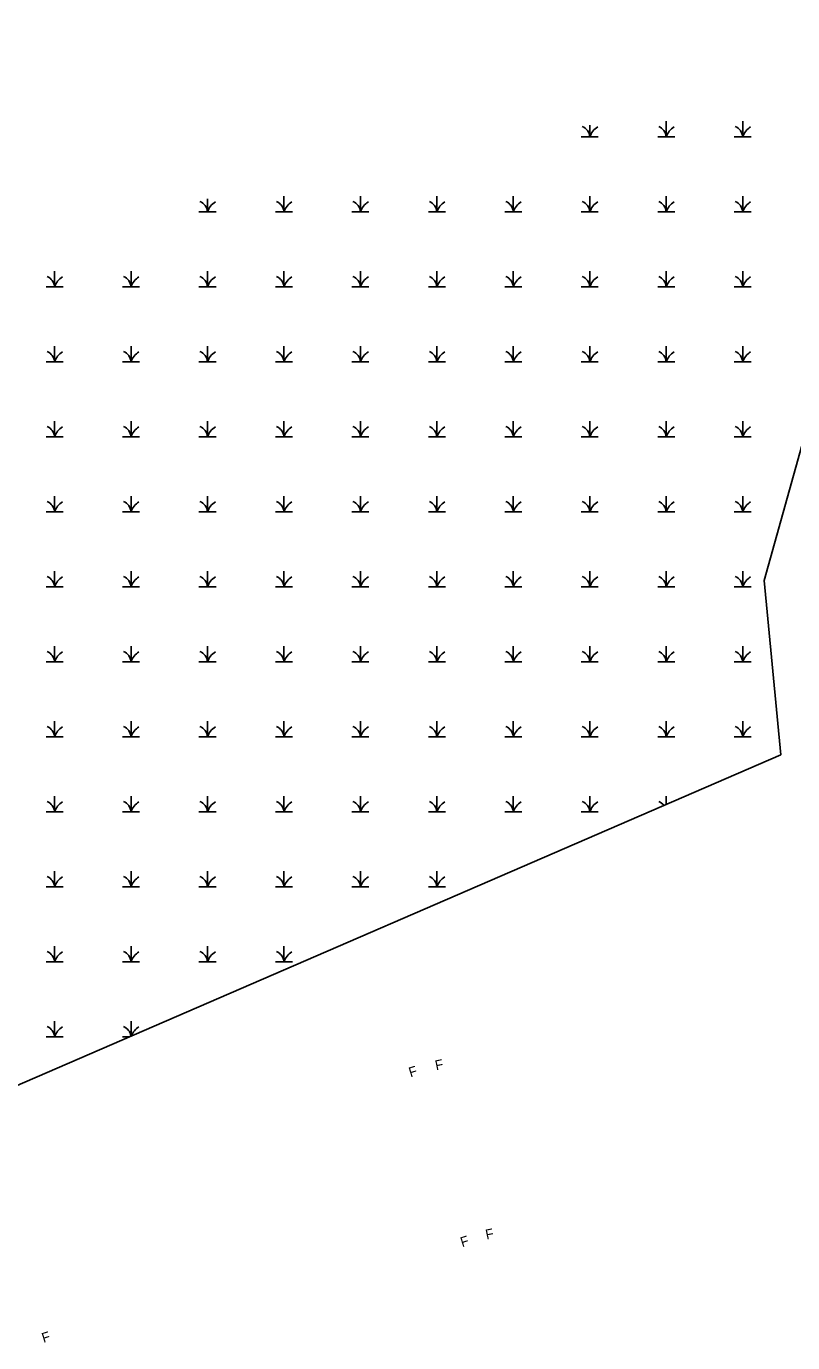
# Model space of a CAD drawing. Extents: x 2166958 to 2178986, y 64620 to 71122.
# Drawn here: x 2168096 to 2168483, y 65520 to 66185 of the extents above; entities that cross this region are included whole.
import ezdxf

# ---------------------------------------------------------------- set-up
doc = ezdxf.new("R2010")
doc.units = 0
for name, color, linetype in [('Default', 7, 'Continuous'), ('Prop Horizontal Alignment', 7, 'Continuous'), ('Prop Horizontal Alignment Station Label', 7, 'Continuous')]:
    doc.layers.add(name, color=color, linetype=linetype)

msp = doc.modelspace()

# ---------------------------------------------------------------- linework, layer by layer
at = {"layer": 'Prop Horizontal Alignment'}
for points in [[(2168476.74, 65816.71), (2168468.47, 65904.83), (2168496.06, 66003.65), (2168524.17, 66100.17), (2168638.33, 66184.78)], [(2168476.74, 65816.71), (2168078.65, 65644.28), (2168068.11, 65657.94), (2168084.89, 65699.98), (2168086.36, 65730.25), (2168062.03, 65791.53), (2168021.16, 65803.33), (2168001.62, 65820.59), (2167975.63, 65861.24), (2167927.1, 65912.33), (2167919.81, 65940.77), (2167923.18, 65952.74), (2167921.92, 65985.66), (2167915.23, 66044.99)]]:
    msp.add_lwpolyline(points, dxfattribs=at)
at = {"layer": 'Prop Horizontal Alignment Station Label'}
for p, q in [((2168418.95, 66128.92), (2168418.95, 66136.82)), ((2168457.56, 66128.92), (2168457.56, 66136.82)), ((2168380.35, 66128.92), (2168380.35, 66134.91)), ((2168376.05, 66128.92), (2168384.65, 66128.92)), ((2168414.65, 66128.92), (2168423.25, 66128.92)), ((2168453.25, 66128.92), (2168461.86, 66128.92)), ((2168187.34, 66091.03), (2168187.34, 66097.6)), ((2168225.95, 66091.03), (2168225.95, 66098.92)), ((2168264.55, 66091.03), (2168264.55, 66098.92)), ((2168303.15, 66091.03), (2168303.15, 66098.92)), ((2168341.75, 66091.03), (2168341.75, 66098.92)), ((2168380.35, 66091.03), (2168380.35, 66098.92)), ((2168418.95, 66091.03), (2168418.95, 66098.92)), ((2168457.56, 66091.03), (2168457.56, 66098.92)), ((2168183.04, 66091.03), (2168191.65, 66091.03)), ((2168221.65, 66091.03), (2168230.25, 66091.03)), ((2168260.25, 66091.03), (2168268.85, 66091.03)), ((2168298.85, 66091.03), (2168307.45, 66091.03)), ((2168337.45, 66091.03), (2168346.05, 66091.03)), ((2168376.05, 66091.03), (2168384.65, 66091.03)), ((2168414.65, 66091.03), (2168423.25, 66091.03)), ((2168453.25, 66091.03), (2168461.86, 66091.03)), ((2168110.14, 66053.14), (2168110.14, 66061.03)), ((2168148.74, 66053.14), (2168148.74, 66061.03)), ((2168187.34, 66053.14), (2168187.34, 66061.03)), ((2168225.95, 66053.14), (2168225.95, 66061.03)), ((2168264.55, 66053.14), (2168264.55, 66061.03)), ((2168303.15, 66053.14), (2168303.15, 66061.03)), ((2168341.75, 66053.14), (2168341.75, 66061.03)), ((2168380.35, 66053.14), (2168380.35, 66061.03)), ((2168418.95, 66053.14), (2168418.95, 66061.03)), ((2168457.56, 66053.14), (2168457.56, 66061.03)), ((2168105.84, 66053.14), (2168114.44, 66053.14)), ((2168144.44, 66053.14), (2168153.04, 66053.14)), ((2168183.04, 66053.14), (2168191.65, 66053.14)), ((2168221.65, 66053.14), (2168230.25, 66053.14)), ((2168260.25, 66053.14), (2168268.85, 66053.14)), ((2168298.85, 66053.14), (2168307.45, 66053.14)), ((2168337.45, 66053.14), (2168346.05, 66053.14)), ((2168376.05, 66053.14), (2168384.65, 66053.14)), ((2168414.65, 66053.14), (2168423.25, 66053.14)), ((2168453.25, 66053.14), (2168461.86, 66053.14)), ((2168110.14, 66015.25), (2168110.14, 66023.14)), ((2168148.74, 66015.25), (2168148.74, 66023.14)), ((2168187.34, 66015.25), (2168187.34, 66023.14)), ((2168225.95, 66015.25), (2168225.95, 66023.14)), ((2168264.55, 66015.25), (2168264.55, 66023.14)), ((2168303.15, 66015.25), (2168303.15, 66023.14)), ((2168341.75, 66015.25), (2168341.75, 66023.14)), ((2168380.35, 66015.25), (2168380.35, 66023.14)), ((2168418.95, 66015.25), (2168418.95, 66023.14)), ((2168457.56, 66015.25), (2168457.56, 66023.14)), ((2168105.84, 66015.25), (2168114.44, 66015.25)), ((2168144.44, 66015.25), (2168153.04, 66015.25)), ((2168183.04, 66015.25), (2168191.65, 66015.25)), ((2168221.65, 66015.25), (2168230.25, 66015.25)), ((2168260.25, 66015.25), (2168268.85, 66015.25)), ((2168298.85, 66015.25), (2168307.45, 66015.25)), ((2168337.45, 66015.25), (2168346.05, 66015.25)), ((2168376.05, 66015.25), (2168384.65, 66015.25)), ((2168414.65, 66015.25), (2168423.25, 66015.25)), ((2168453.25, 66015.25), (2168461.86, 66015.25)), ((2168110.14, 65977.36), (2168110.14, 65985.25)), ((2168148.74, 65977.36), (2168148.74, 65985.25)), ((2168187.34, 65977.36), (2168187.34, 65985.25)), ((2168225.95, 65977.36), (2168225.95, 65985.25)), ((2168264.55, 65977.36), (2168264.55, 65985.25)), ((2168303.15, 65977.36), (2168303.15, 65985.25)), ((2168341.75, 65977.36), (2168341.75, 65985.25)), ((2168380.35, 65977.36), (2168380.35, 65985.25)), ((2168418.95, 65977.36), (2168418.95, 65985.25)), ((2168457.56, 65977.36), (2168457.56, 65985.25)), ((2168105.84, 65977.36), (2168114.44, 65977.36)), ((2168144.44, 65977.36), (2168153.04, 65977.36)), ((2168183.04, 65977.36), (2168191.65, 65977.36)), ((2168221.65, 65977.36), (2168230.25, 65977.36)), ((2168260.25, 65977.36), (2168268.85, 65977.36)), ((2168298.85, 65977.36), (2168307.45, 65977.36)), ((2168337.45, 65977.36), (2168346.05, 65977.36)), ((2168376.05, 65977.36), (2168384.65, 65977.36)), ((2168414.65, 65977.36), (2168423.25, 65977.36)), ((2168453.25, 65977.36), (2168461.86, 65977.36)), ((2168110.14, 65939.47), (2168110.14, 65947.36)), ((2168148.74, 65939.47), (2168148.74, 65947.36)), ((2168187.34, 65939.47), (2168187.34, 65947.36)), ((2168225.95, 65939.47), (2168225.95, 65947.36)), ((2168264.55, 65939.47), (2168264.55, 65947.36)), ((2168303.15, 65939.47), (2168303.15, 65947.36)), ((2168341.75, 65939.47), (2168341.75, 65947.36)), ((2168380.35, 65939.47), (2168380.35, 65947.36)), ((2168418.95, 65939.47), (2168418.95, 65947.36)), ((2168457.56, 65939.47), (2168457.56, 65947.36)), ((2168105.84, 65939.47), (2168114.44, 65939.47)), ((2168144.44, 65939.47), (2168153.04, 65939.47)), ((2168183.04, 65939.47), (2168191.65, 65939.47)), ((2168221.65, 65939.47), (2168230.25, 65939.47)), ((2168260.25, 65939.47), (2168268.85, 65939.47)), ((2168298.85, 65939.47), (2168307.45, 65939.47)), ((2168337.45, 65939.47), (2168346.05, 65939.47)), ((2168376.05, 65939.47), (2168384.65, 65939.47)), ((2168414.65, 65939.47), (2168423.25, 65939.47)), ((2168453.25, 65939.47), (2168461.86, 65939.47)), ((2168110.14, 65901.58), (2168110.14, 65909.47)), ((2168148.74, 65901.58), (2168148.74, 65909.47)), ((2168187.34, 65901.58), (2168187.34, 65909.47)), ((2168225.95, 65901.58), (2168225.95, 65909.47)), ((2168264.55, 65901.58), (2168264.55, 65909.47)), ((2168303.15, 65901.58), (2168303.15, 65909.47)), ((2168341.75, 65901.58), (2168341.75, 65909.47)), ((2168380.35, 65901.58), (2168380.35, 65909.47)), ((2168418.95, 65901.58), (2168418.95, 65909.47)), ((2168457.56, 65901.58), (2168457.56, 65909.47)), ((2168105.84, 65901.58), (2168114.44, 65901.58)), ((2168144.44, 65901.58), (2168153.04, 65901.58)), ((2168183.04, 65901.58), (2168191.65, 65901.58)), ((2168221.65, 65901.58), (2168230.25, 65901.58)), ((2168260.25, 65901.58), (2168268.85, 65901.58)), ((2168298.85, 65901.58), (2168307.45, 65901.58)), ((2168337.45, 65901.58), (2168346.05, 65901.58)), ((2168376.05, 65901.58), (2168384.65, 65901.58)), ((2168414.65, 65901.58), (2168423.25, 65901.58)), ((2168453.25, 65901.58), (2168461.86, 65901.58)), ((2168110.14, 65863.69), (2168110.14, 65871.58)), ((2168148.74, 65863.69), (2168148.74, 65871.58)), ((2168187.34, 65863.69), (2168187.34, 65871.58)), ((2168225.95, 65863.69), (2168225.95, 65871.58)), ((2168264.55, 65863.69), (2168264.55, 65871.58)), ((2168303.15, 65863.69), (2168303.15, 65871.58)), ((2168341.75, 65863.69), (2168341.75, 65871.58)), ((2168380.35, 65863.69), (2168380.35, 65871.58)), ((2168418.95, 65863.69), (2168418.95, 65871.58)), ((2168457.56, 65863.69), (2168457.56, 65871.58)), ((2168105.84, 65863.69), (2168114.44, 65863.69)), ((2168144.44, 65863.69), (2168153.04, 65863.69)), ((2168183.04, 65863.69), (2168191.65, 65863.69)), ((2168221.65, 65863.69), (2168230.25, 65863.69)), ((2168260.25, 65863.69), (2168268.85, 65863.69)), ((2168298.85, 65863.69), (2168307.45, 65863.69)), ((2168337.45, 65863.69), (2168346.05, 65863.69)), ((2168376.05, 65863.69), (2168384.65, 65863.69)), ((2168414.65, 65863.69), (2168423.25, 65863.69)), ((2168453.25, 65863.69), (2168461.86, 65863.69)), ((2168110.14, 65825.8), (2168110.14, 65833.69)), ((2168148.74, 65825.8), (2168148.74, 65833.69)), ((2168187.34, 65825.8), (2168187.34, 65833.69)), ((2168225.95, 65825.8), (2168225.95, 65833.69)), ((2168264.55, 65825.8), (2168264.55, 65833.69)), ((2168303.15, 65825.8), (2168303.15, 65833.69)), ((2168341.75, 65825.8), (2168341.75, 65833.69)), ((2168380.35, 65825.8), (2168380.35, 65833.69)), ((2168418.95, 65825.8), (2168418.95, 65833.69)), ((2168457.56, 65825.8), (2168457.56, 65833.69)), ((2168105.84, 65825.8), (2168114.44, 65825.8)), ((2168144.44, 65825.8), (2168153.04, 65825.8)), ((2168183.04, 65825.8), (2168191.65, 65825.8)), ((2168221.65, 65825.8), (2168230.25, 65825.8)), ((2168260.25, 65825.8), (2168268.85, 65825.8)), ((2168298.85, 65825.8), (2168307.45, 65825.8)), ((2168337.45, 65825.8), (2168346.05, 65825.8)), ((2168376.05, 65825.8), (2168384.65, 65825.8)), ((2168414.65, 65825.8), (2168423.25, 65825.8)), ((2168453.25, 65825.8), (2168461.86, 65825.8)), ((2168110.14, 65787.91), (2168110.14, 65795.8)), ((2168148.74, 65787.91), (2168148.74, 65795.8)), ((2168187.34, 65787.91), (2168187.34, 65795.8)), ((2168225.95, 65787.91), (2168225.95, 65795.8)), ((2168264.55, 65787.91), (2168264.55, 65795.8)), ((2168303.15, 65787.91), (2168303.15, 65795.8)), ((2168341.75, 65787.91), (2168341.75, 65795.8)), ((2168380.35, 65787.91), (2168380.35, 65795.8)), ((2168418.95, 65791.68), (2168418.95, 65795.8)), ((2168105.84, 65787.91), (2168114.44, 65787.91)), ((2168144.44, 65787.91), (2168153.04, 65787.91)), ((2168183.04, 65787.91), (2168191.65, 65787.91)), ((2168221.65, 65787.91), (2168230.25, 65787.91)), ((2168260.25, 65787.91), (2168268.85, 65787.91)), ((2168298.85, 65787.91), (2168307.45, 65787.91)), ((2168337.45, 65787.91), (2168346.05, 65787.91)), ((2168376.05, 65787.91), (2168384.65, 65787.91)), ((2168110.14, 65750.02), (2168110.14, 65757.91)), ((2168148.74, 65750.02), (2168148.74, 65757.91)), ((2168187.34, 65750.02), (2168187.34, 65757.91)), ((2168225.95, 65750.02), (2168225.95, 65757.91)), ((2168264.55, 65750.02), (2168264.55, 65757.91)), ((2168303.15, 65750.02), (2168303.15, 65757.91)), ((2168105.84, 65750.02), (2168114.44, 65750.02)), ((2168144.44, 65750.02), (2168153.04, 65750.02)), ((2168183.04, 65750.02), (2168191.65, 65750.02)), ((2168221.65, 65750.02), (2168230.25, 65750.02)), ((2168260.25, 65750.02), (2168268.85, 65750.02)), ((2168298.85, 65750.02), (2168307.45, 65750.02)), ((2168110.14, 65712.13), (2168110.14, 65720.02)), ((2168148.74, 65712.13), (2168148.74, 65720.02)), ((2168187.34, 65712.13), (2168187.34, 65720.02)), ((2168225.95, 65712.13), (2168225.95, 65720.02)), ((2168105.84, 65712.13), (2168114.44, 65712.13)), ((2168144.44, 65712.13), (2168153.04, 65712.13)), ((2168183.04, 65712.13), (2168191.65, 65712.13)), ((2168221.65, 65712.13), (2168230.25, 65712.13)), ((2168110.14, 65674.24), (2168110.14, 65682.13)), ((2168148.74, 65674.64), (2168148.74, 65682.13)), ((2168105.84, 65674.24), (2168114.44, 65674.24)), ((2168144.44, 65674.24), (2168147.82, 65674.24))]:
    msp.add_line(p, q, dxfattribs=at)
for centre, radius, start, end in [((2168374.22, 66128.48), 6.15, 4.14034, 67.53497), ((2168389.47, 66125.89), 9.61, 122.12745, 161.62219), ((2168412.82, 66128.48), 6.15, 4.14034, 67.53497), ((2168428.07, 66125.89), 9.61, 122.12745, 161.62219), ((2168451.42, 66128.48), 6.15, 4.14034, 67.53497), ((2168466.68, 66125.89), 9.61, 122.12745, 161.62219), ((2168181.21, 66090.59), 6.15, 4.14034, 67.53497), ((2168196.47, 66088), 9.61, 122.12745, 161.62219), ((2168219.81, 66090.59), 6.15, 4.14034, 67.53497), ((2168235.07, 66088), 9.61, 122.12745, 161.62219), ((2168258.41, 66090.59), 6.15, 4.14034, 67.53497), ((2168273.67, 66088), 9.61, 122.12745, 161.62219), ((2168297.02, 66090.59), 6.15, 4.14034, 67.53497), ((2168312.27, 66088), 9.61, 122.12745, 161.62219), ((2168335.62, 66090.59), 6.15, 4.14034, 67.53497), ((2168350.87, 66088), 9.61, 122.12745, 161.62219), ((2168374.22, 66090.59), 6.15, 4.14034, 67.53497), ((2168389.47, 66088), 9.61, 122.12745, 161.62219), ((2168412.82, 66090.59), 6.15, 4.14034, 67.53497), ((2168428.07, 66088), 9.61, 122.12745, 161.62219), ((2168451.42, 66090.59), 6.15, 4.14034, 67.53497), ((2168466.68, 66088), 9.61, 122.12745, 161.62219), ((2168104.01, 66052.7), 6.15, 4.14034, 67.53497), ((2168119.26, 66050.11), 9.61, 122.12745, 161.62219), ((2168142.61, 66052.7), 6.15, 4.14034, 67.53497), ((2168157.86, 66050.11), 9.61, 122.12745, 161.62219), ((2168181.21, 66052.7), 6.15, 4.14034, 67.53497), ((2168196.47, 66050.11), 9.61, 122.12745, 161.62219), ((2168219.81, 66052.7), 6.15, 4.14034, 67.53497), ((2168235.07, 66050.11), 9.61, 122.12745, 161.62219), ((2168258.41, 66052.7), 6.15, 4.14034, 67.53497), ((2168273.67, 66050.11), 9.61, 122.12745, 161.62219), ((2168297.02, 66052.7), 6.15, 4.14034, 67.53497), ((2168312.27, 66050.11), 9.61, 122.12745, 161.62219), ((2168335.62, 66052.7), 6.15, 4.14034, 67.53497), ((2168350.87, 66050.11), 9.61, 122.12745, 161.62219), ((2168374.22, 66052.7), 6.15, 4.14034, 67.53497), ((2168389.47, 66050.11), 9.61, 122.12745, 161.62219), ((2168412.82, 66052.7), 6.15, 4.14034, 67.53497), ((2168428.07, 66050.11), 9.61, 122.12745, 161.62219), ((2168451.42, 66052.7), 6.15, 4.14034, 67.53497), ((2168466.68, 66050.11), 9.61, 122.12745, 161.62219), ((2168104.01, 66014.81), 6.15, 4.14034, 67.53497), ((2168119.26, 66012.22), 9.61, 122.12745, 161.62219), ((2168142.61, 66014.81), 6.15, 4.14034, 67.53497), ((2168157.86, 66012.22), 9.61, 122.12745, 161.62219), ((2168181.21, 66014.81), 6.15, 4.14034, 67.53497), ((2168196.47, 66012.22), 9.61, 122.12745, 161.62219), ((2168219.81, 66014.81), 6.15, 4.14034, 67.53497), ((2168235.07, 66012.22), 9.61, 122.12745, 161.62219), ((2168258.41, 66014.81), 6.15, 4.14034, 67.53497), ((2168273.67, 66012.22), 9.61, 122.12745, 161.62219), ((2168297.02, 66014.81), 6.15, 4.14034, 67.53497), ((2168312.27, 66012.22), 9.61, 122.12745, 161.62219), ((2168335.62, 66014.81), 6.15, 4.14034, 67.53497), ((2168350.87, 66012.22), 9.61, 122.12745, 161.62219), ((2168374.22, 66014.81), 6.15, 4.14034, 67.53497), ((2168389.47, 66012.22), 9.61, 122.12745, 161.62219), ((2168412.82, 66014.81), 6.15, 4.14034, 67.53497), ((2168428.07, 66012.22), 9.61, 122.12745, 161.62219), ((2168451.42, 66014.81), 6.15, 4.14034, 67.53497), ((2168466.68, 66012.22), 9.61, 122.12745, 161.62219), ((2168104.01, 65976.92), 6.15, 4.14034, 67.53497), ((2168119.26, 65974.33), 9.61, 122.12745, 161.62219), ((2168142.61, 65976.92), 6.15, 4.14034, 67.53497), ((2168157.86, 65974.33), 9.61, 122.12745, 161.62219), ((2168181.21, 65976.92), 6.15, 4.14034, 67.53497), ((2168196.47, 65974.33), 9.61, 122.12745, 161.62219), ((2168219.81, 65976.92), 6.15, 4.14034, 67.53497), ((2168235.07, 65974.33), 9.61, 122.12745, 161.62219), ((2168258.41, 65976.92), 6.15, 4.14034, 67.53497), ((2168273.67, 65974.33), 9.61, 122.12745, 161.62219), ((2168297.02, 65976.92), 6.15, 4.14034, 67.53497), ((2168312.27, 65974.33), 9.61, 122.12745, 161.62219), ((2168335.62, 65976.92), 6.15, 4.14034, 67.53497), ((2168350.87, 65974.33), 9.61, 122.12745, 161.62219), ((2168374.22, 65976.92), 6.15, 4.14034, 67.53497), ((2168389.47, 65974.33), 9.61, 122.12745, 161.62219), ((2168412.82, 65976.92), 6.15, 4.14034, 67.53497), ((2168428.07, 65974.33), 9.61, 122.12745, 161.62219), ((2168451.42, 65976.92), 6.15, 4.14034, 67.53497), ((2168466.68, 65974.33), 9.61, 122.12745, 161.62219), ((2168104.01, 65939.03), 6.15, 4.14034, 67.53497), ((2168119.26, 65936.44), 9.61, 122.12745, 161.62219), ((2168142.61, 65939.03), 6.15, 4.14034, 67.53497), ((2168157.86, 65936.44), 9.61, 122.12745, 161.62219), ((2168181.21, 65939.03), 6.15, 4.14034, 67.53497), ((2168196.47, 65936.44), 9.61, 122.12745, 161.62219), ((2168219.81, 65939.03), 6.15, 4.14034, 67.53497), ((2168235.07, 65936.44), 9.61, 122.12745, 161.62219), ((2168258.41, 65939.03), 6.15, 4.14034, 67.53497), ((2168273.67, 65936.44), 9.61, 122.12745, 161.62219), ((2168297.02, 65939.03), 6.15, 4.14034, 67.53497), ((2168312.27, 65936.44), 9.61, 122.12745, 161.62219), ((2168335.62, 65939.03), 6.15, 4.14034, 67.53497), ((2168350.87, 65936.44), 9.61, 122.12745, 161.62219), ((2168374.22, 65939.03), 6.15, 4.14034, 67.53497), ((2168389.47, 65936.44), 9.61, 122.12745, 161.62219), ((2168412.82, 65939.03), 6.15, 4.14034, 67.53497), ((2168428.07, 65936.44), 9.61, 122.12745, 161.62219), ((2168451.42, 65939.03), 6.15, 4.14034, 67.53497), ((2168466.68, 65936.44), 9.61, 122.12745, 161.62219), ((2168104.01, 65901.14), 6.15, 4.14034, 67.53497), ((2168119.26, 65898.55), 9.61, 122.12745, 161.62219), ((2168142.61, 65901.14), 6.15, 4.14034, 67.53497), ((2168157.86, 65898.55), 9.61, 122.12745, 161.62219), ((2168181.21, 65901.14), 6.15, 4.14034, 67.53497), ((2168196.47, 65898.55), 9.61, 122.12745, 161.62219), ((2168219.81, 65901.14), 6.15, 4.14034, 67.53497), ((2168235.07, 65898.55), 9.61, 122.12745, 161.62219), ((2168258.41, 65901.14), 6.15, 4.14034, 67.53497), ((2168273.67, 65898.55), 9.61, 122.12745, 161.62219), ((2168297.02, 65901.14), 6.15, 4.14034, 67.53497), ((2168312.27, 65898.55), 9.61, 122.12745, 161.62219), ((2168335.62, 65901.14), 6.15, 4.14034, 67.53497), ((2168350.87, 65898.55), 9.61, 122.12745, 161.62219), ((2168374.22, 65901.14), 6.15, 4.14034, 67.53497), ((2168389.47, 65898.55), 9.61, 122.12745, 161.62219), ((2168412.82, 65901.14), 6.15, 4.14034, 67.53497), ((2168428.07, 65898.55), 9.61, 122.12745, 161.62219), ((2168451.42, 65901.14), 6.15, 4.14034, 67.53497), ((2168466.68, 65898.55), 9.61, 122.12745, 161.62219), ((2168104.01, 65863.25), 6.15, 4.14034, 67.53497), ((2168119.26, 65860.66), 9.61, 122.12745, 161.62219), ((2168142.61, 65863.25), 6.15, 4.14034, 67.53497), ((2168157.86, 65860.66), 9.61, 122.12745, 161.62219), ((2168181.21, 65863.25), 6.15, 4.14034, 67.53497), ((2168196.47, 65860.66), 9.61, 122.12745, 161.62219), ((2168219.81, 65863.25), 6.15, 4.14034, 67.53497), ((2168235.07, 65860.66), 9.61, 122.12745, 161.62219), ((2168258.41, 65863.25), 6.15, 4.14034, 67.53497), ((2168273.67, 65860.66), 9.61, 122.12745, 161.62219), ((2168297.02, 65863.25), 6.15, 4.14034, 67.53497), ((2168312.27, 65860.66), 9.61, 122.12745, 161.62219), ((2168335.62, 65863.25), 6.15, 4.14034, 67.53497), ((2168350.87, 65860.66), 9.61, 122.12745, 161.62219), ((2168374.22, 65863.25), 6.15, 4.14034, 67.53497), ((2168389.47, 65860.66), 9.61, 122.12745, 161.62219), ((2168412.82, 65863.25), 6.15, 4.14034, 67.53497), ((2168428.07, 65860.66), 9.61, 122.12745, 161.62219), ((2168451.42, 65863.25), 6.15, 4.14034, 67.53497), ((2168466.68, 65860.66), 9.61, 122.12745, 161.62219), ((2168104.01, 65825.36), 6.15, 4.14034, 67.53497), ((2168119.26, 65822.77), 9.61, 122.12745, 161.62219), ((2168142.61, 65825.36), 6.15, 4.14034, 67.53497), ((2168157.86, 65822.77), 9.61, 122.12745, 161.62219), ((2168181.21, 65825.36), 6.15, 4.14034, 67.53497), ((2168196.47, 65822.77), 9.61, 122.12745, 161.62219), ((2168219.81, 65825.36), 6.15, 4.14034, 67.53497), ((2168235.07, 65822.77), 9.61, 122.12745, 161.62219), ((2168258.41, 65825.36), 6.15, 4.14034, 67.53497), ((2168273.67, 65822.77), 9.61, 122.12745, 161.62219), ((2168297.02, 65825.36), 6.15, 4.14034, 67.53497), ((2168312.27, 65822.77), 9.61, 122.12745, 161.62219), ((2168335.62, 65825.36), 6.15, 4.14034, 67.53497), ((2168350.87, 65822.77), 9.61, 122.12745, 161.62219), ((2168374.22, 65825.36), 6.15, 4.14034, 67.53497), ((2168389.47, 65822.77), 9.61, 122.12745, 161.62219), ((2168412.82, 65825.36), 6.15, 4.14034, 67.53497), ((2168428.07, 65822.77), 9.61, 122.12745, 161.62219), ((2168451.42, 65825.36), 6.15, 4.14034, 67.53497), ((2168466.68, 65822.77), 9.61, 122.12745, 161.62219), ((2168104.01, 65787.47), 6.15, 4.14034, 67.53497), ((2168119.26, 65784.88), 9.61, 122.12745, 161.62219), ((2168142.61, 65787.47), 6.15, 4.14034, 67.53497), ((2168157.86, 65784.88), 9.61, 122.12745, 161.62219), ((2168181.21, 65787.47), 6.15, 4.14034, 67.53497), ((2168196.47, 65784.88), 9.61, 122.12745, 161.62219), ((2168219.81, 65787.47), 6.15, 4.14034, 67.53497), ((2168235.07, 65784.88), 9.61, 122.12745, 161.62219), ((2168258.41, 65787.47), 6.15, 4.14034, 67.53497), ((2168273.67, 65784.88), 9.61, 122.12745, 161.62219), ((2168297.02, 65787.47), 6.15, 4.14034, 67.53497), ((2168312.27, 65784.88), 9.61, 122.12745, 161.62219), ((2168335.62, 65787.47), 6.15, 4.14034, 67.53497), ((2168350.87, 65784.88), 9.61, 122.12745, 161.62219), ((2168374.22, 65787.47), 6.15, 4.14034, 67.53497), ((2168389.47, 65784.88), 9.61, 122.12745, 161.62219), ((2168412.82, 65787.47), 6.15, 36.84065, 67.53497), ((2168104.01, 65749.58), 6.15, 4.14034, 67.53497), ((2168119.26, 65746.99), 9.61, 122.12745, 161.62219), ((2168142.61, 65749.58), 6.15, 4.14034, 67.53497), ((2168157.86, 65746.99), 9.61, 122.12745, 161.62219), ((2168181.21, 65749.58), 6.15, 4.14034, 67.53497), ((2168196.47, 65746.99), 9.61, 122.12745, 161.62219), ((2168219.81, 65749.58), 6.15, 4.14034, 67.53497), ((2168235.07, 65746.99), 9.61, 122.12745, 161.62219), ((2168258.41, 65749.58), 6.15, 4.14034, 67.53497), ((2168273.67, 65746.99), 9.61, 122.12745, 161.62219), ((2168297.02, 65749.58), 6.15, 4.14034, 67.53497), ((2168312.27, 65746.99), 9.61, 122.12745, 161.62219), ((2168104.01, 65711.69), 6.15, 4.14034, 67.53497), ((2168119.26, 65709.1), 9.61, 122.12745, 161.62219), ((2168142.61, 65711.69), 6.15, 4.14034, 67.53497), ((2168157.86, 65709.1), 9.61, 122.12745, 161.62219), ((2168181.21, 65711.69), 6.15, 4.14034, 67.53497), ((2168196.47, 65709.1), 9.61, 122.12745, 161.62219), ((2168219.81, 65711.69), 6.15, 4.14034, 67.53497), ((2168235.07, 65709.1), 9.61, 122.12745, 161.62219), ((2168104.01, 65673.8), 6.15, 4.14034, 67.53497), ((2168119.26, 65671.21), 9.61, 122.12745, 161.62219), ((2168142.61, 65673.8), 6.15, 7.72029, 67.53497), ((2168157.86, 65671.21), 9.61, 122.12745, 158.62077)]:
    msp.add_arc(centre, radius, start, end, dxfattribs=at)

# ---------------------------------------------------------------- texts
at = {"layer": 'Default'}
for rotation, p in [(17.18233, (2168289.84, 65653.76)), (11.84231, (2168302.8, 65657.32)), (17.18233, (2168315.91, 65567.98)), (11.84231, (2168328.25, 65571.84)), (17.18233, (2168104.56, 65519.6))]:
    msp.add_text('F', height=5, rotation=rotation, dxfattribs=at).set_placement(p)

doc.saveas('drawing.dxf')
